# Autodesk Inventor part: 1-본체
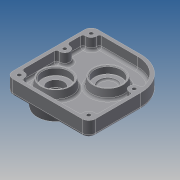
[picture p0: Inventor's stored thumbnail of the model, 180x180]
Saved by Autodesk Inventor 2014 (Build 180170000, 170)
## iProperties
Created: 2015-11
Part Number: 1-본체
Material: Generic
Document SubType Name: Modeling
Designer: kb541
Density: 1 g/cm^3
Appearance: Default
Author: kb541
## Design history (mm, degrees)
sketch "스케치1"
  geometry: L1 (0, 0)-(100, 0); L2 (100, 0)-(100, 63); L3 (60, 103)-(0, 103); L4 (0, 103)-(0, 0); A1 r 40 centre (60, 63) between (100, 63) and (60, 103)
  constraints: 8 end point, 2 parallel, 2 point on circle, 2 tangent, 1 centre point, 1 horizontal, 1 perpendicular
  dimensions: "d0" = 103 distance of L3.end L1.start; "d1" = 100 distance of L1.start L1.end; "d2" = 40 radius of A1
extrude "돌출1" new body sketch "스케치1" stored distance "d3" = 18; taper "d4" = 0 deg
feature "쉘1" dims "d5" = 4
fillet "모깎기1" dims "d6" = 8
sketch "스케치3"
  geometry: L1 (100, 8)-(100, 63) reference; L2 (0, 95)-(0, 8) reference; L3 (8, 0)-(92, 0) reference; C1 r 6 at (8, 95); C2 r 6 at (8, 8); C3 r 6 at (92, 8); C4 r 6 at (92, 63); C5 r 6 at (8, 63); A1 r 8 centre (92, 8) between (92, 0) and (100, 8) reference; A2 r 8 centre (8, 95) between (8, 103) and (0, 95) reference; A3 r 8 centre (8, 8) between (0, 8) and (8, 0) reference; 1 further point
  constraints: 5 centre point, 3 coincident, 1 horizontal alignment
  dimensions: "d7" = 12 diameter of C1; "d8" = 12 diameter of C2; "d9" = 12 diameter of C3; "d10" = 12 diameter of C4; "d11" = 12 diameter of C5; "d12" = 8 distance from line of L2 C5.centre; "d13" = 63 distance from line of L3 C5.centre; "d14" = 8 distance from line of L1 C4.centre
extrude "돌출2" join sketch "스케치3" distance "d15" = 18; taper "d16" = 0 deg
sketch "스케치4"
  geometry: L1 (-92, 0)-(-8, 0) reference; L2 (0, 8)-(0, 95) reference; L3 (-100, 63)-(-100, 8) reference; A1 r 8 centre (-8, 8) between (-8, 0) and (0, 8) reference; A2 r 8 centre (-8, 95) between (0, 95) and (-8, 103) reference; A3 r 8 centre (-92, 8) between (-100, 8) and (-92, 0) reference; 6 further points
  constraints: 3 coincident
  dimensions: "d17" = 63 distance from line of L1 point (-92, 63); "d18" = 8 distance from line of L3 point (-92, 63); "d19" = 8 distance from line of L2 point (-8, 63); "d20" = 63 distance from line of L1 point (-8, 63)
hole "구멍1" sketch "스케치4" at (-8, 95), (-8, 8), (-92, 8), (-92, 63), (-8, 63) diameter "d21" = 4.5; stored, may be unused: countersink angle "d25" = 90 deg, drill point angle "d27" = 118 deg; dims "d22" = 6, "d23" = 8, "d24" = 4.4, "d26" = 8
sketch "스케치5"
  geometry: L1 (-4.472, -4)-(79.528, -4) reference; L2 (-12.472, 91)-(-12.472, 4) reference; C1 r 20 at (47.528, 59); C2 r 20 at (17.528, 26); 1 further point
  constraints: 2 centre point
  dimensions: "d28" = 40 diameter of C1; "d29" = 40 diameter of C2; "d30" = 63 distance from line of L1 C1.centre; "d31" = 60 distance from line of L2 C1.centre; "d32" = 30 distance from line of L1 C2.centre; "d33" = 30 distance from line of L2 C2.centre
extrude "돌출3" join sketch "스케치5" distance "d34" = 11; taper "d35" = -10 deg
node "작업 평면1"
sketch "스케치6"
  geometry: L1 (33.94, -3)-(70.06, -3) reference; L2 (52, -3)-(52, -14); L3 (52, -14)-(41, -14); L4 (41, -14)-(41, -12); L5 (41, -12)-(36, -12); L6 (36, -12)-(36, -3); L7 (36, -3)-(52, -3); 1 further point
  constraints: 12 end point, 3 perpendicular, 2 parallel, 1 collinear, 1 midpoint, 1 point on line
  dimensions: "d37" = 11 distance of L2.start L2.end; "d38" = 11 distance of L2.end L3.end; "d39" = 2 distance of L3.end L4.end; "d40" = 5 distance of L4.end L5.end
revolve "회전1" sketch "스케치6" stored, may be unused: angle "d41" = 90 deg
fillet "모깎기2" dims "d42" = 2
node "작업 평면2"
sketch "스케치7"
  geometry: 1 further point
sketch "스케치8"
  geometry: L1 (-92, 0)-(-8, 0) reference; L2 (0, 8)-(0, 95) reference; C1 r 25 at (-30, 30); 1 further point
  constraints: 1 centre point
  dimensions: "d44" = 50 diameter of C1; "d45" = 30 distance from line of L1 C1.centre; "d46" = 30 distance from line of L2 C1.centre
extrude "돌출4" join sketch "스케치8" distance "d47" = 15; taper "d48" = -10 deg
sketch "스케치9"
  geometry: L1 (44.355, -33)-(-0.355, -33) reference; L2 (3.94, -3)-(40.06, -3) reference; L3 (22, -3)-(22, -33); L4 (22, -33)-(36, -33); L5 (36, -33)-(36, -22); L6 (36, -22)-(34, -22); L7 (34, -22)-(34, -20); L8 (34, -20)-(32, -20); L9 (22, -3)-(38, -3); L10 (38, -3)-(38, -12); L11 (38, -12)-(32, -12); L12 (32, -12)-(32, -20); 1 further point
  constraints: 20 end point, 5 perpendicular, 2 midpoint, 2 parallel, 2 point on line
  dimensions: "d49" = 14 distance of L3.end L4.end; "d50" = 11 distance of L4.end L5.end; "d51" = 2 distance of L5.end L6.end; "d52" = 2 distance of L6.end L7.end; "d53" = 2 distance of L7.end L8.end; "d54" = 16 distance of L3.start L9.end; "d55" = 9 distance of L9.end L10.end
revolve "회전2" sketch "스케치9" stored, may be unused: angle "d56" = 90 deg
fillet "모깎기4" dims "d58" = 3
fillet "모깎기3" dims "d57" = 3
fillet "모깎기5" dims "d59" = 3
sketch "스케치10"
  geometry: C1 r 14 at (0, 0) reference; 2 further points
  constraints: 1 vertical alignment
  dimensions: "d60" = 18 distance of C1.centre point (0, 18)
hole "구멍2" sketch "스케치10" at (0, 18) diameter "d61" = 2.459; stored, may be unused: countersink angle "d65" = 90 deg, drill point angle "d67" = 118 deg; dims "d62" = 8, "d63" = 8, "d64" = 4.4, "d66" = 10
fillet "모깎기6" dims "d71" = 3
sketch "스케치11"
  geometry: L1 (0, 8)-(0, 95) reference; L2 (-8, 103)-(-60, 103) reference; 2 further points
  constraints: 1 other
  dimensions: "d72" = 40 distance from line of L1 point (-40, 83); "d73" = 20 distance from line of L2 point (-40, 83)
feature "엠보싱1" sketch "스케치11" dims "d0" = 103, "d1" = 100, "d2" = 40, "d74" = 0.5, "d75" = 0
chamfer "모따기1" distance "d76" = 1; stored, may be unused: second distance "d77" = 2, angle "d78" = 45 deg
fillet "모깎기7" dims "d79" = 2
fillet "모깎기8" dims "d80" = 0.3
node "솔리드1"
pattern_circular "원형 패턴1" dims angle "d69" = 360 deg
other parameters: "d36" = -63
